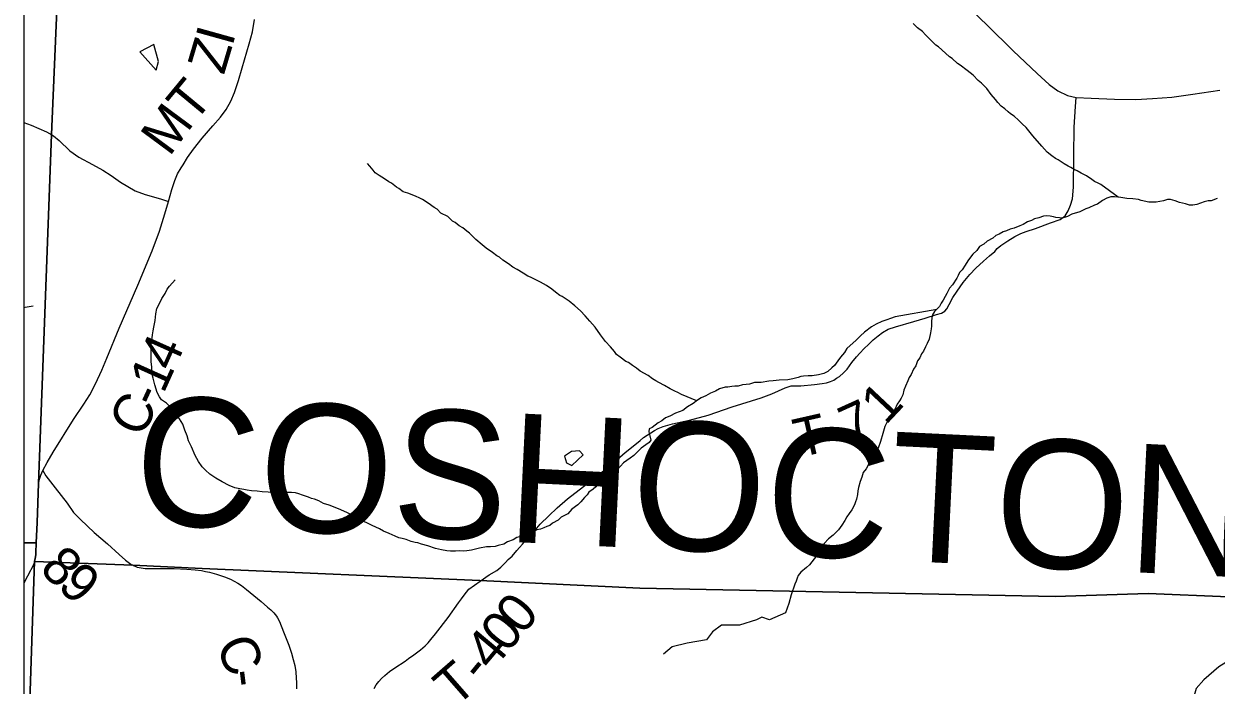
# Model space of a CAD drawing. Extents: x 0 to 34, y 0 to 22.
# Drawn here: x 2.1 to 3.853, y 16.238 to 17.211 of the extents above; entities that cross this region are included whole.
import ezdxf

# ---------------------------------------------------------------- set-up
doc = ezdxf.new("R2010")
doc.units = 0
for name, color, linetype in [('GM_X_Corporation', 7, 'Continuous'), ('GM_X_County_Road', 7, 'Continuous'), ('GM_X_County_Road_Text', 7, 'Continuous'), ('GM_X_County_Text', 7, 'Continuous'), ('GM_X_Minor_Lake', 7, 'Continuous'), ('GM_X_Minor_River', 7, 'Continuous'), ('GM_X_Township_Road', 7, 'Continuous'), ('GM_X_Township_Road_Text', 7, 'Continuous'), ('SH_Data', 7, 'Continuous')]:
    doc.layers.add(name, color=color, linetype=linetype)

msp = doc.modelspace()

# ---------------------------------------------------------------- linework, layer by layer
at = {"layer": 'GM_X_Corporation'}
for points in [[(8.9, 20.9), (2.1, 20.9), (2.1, 16.4477), (2.1182, 16.4474), (2.1176, 16.4327), (2.1175, 16.4298), (2.1166, 16.4244), (2.1155, 16.4201), (2.2605, 16.4147), (2.3623, 16.41), (2.7707, 16.392), (3.0057, 16.3809), (3.6165, 16.3686), (3.7537, 16.3728), (3.9899, 16.3631), (4.4958, 16.358), (4.9914, 16.3477), (5.6931, 16.3352)], [(2.1, 20.9), (2.1, 16.4477), (2.1182, 16.4474), (2.1195, 16.4774), (2.1214, 16.5347), (2.1408, 17.0483), (2.1838, 18.0574), (2.1889, 18.2792), (2.187, 18.2863), (2.1862, 18.2947), (2.1862, 18.3057), (2.1873, 18.3376), (2.1879, 18.3572), (2.1884, 18.4113), (2.1894, 18.4715), (2.1995, 18.7384)], [(2.1838, 18.0574), (2.1408, 17.0483), (2.1214, 16.5347), (2.1195, 16.4774), (2.1182, 16.4474), (2.1176, 16.4327), (2.1175, 16.4298), (2.1166, 16.4244), (2.1155, 16.4201), (2.2605, 16.4147), (2.3623, 16.41), (2.7707, 16.392), (3.0057, 16.3809), (3.6165, 16.3686), (3.7537, 16.3728), (3.9899, 16.3631)], [(5.6931, 16.3352), (4.9914, 16.3477), (4.4958, 16.358), (3.9899, 16.3631), (3.7537, 16.3728), (3.6165, 16.3686), (3.0057, 16.3809), (2.7707, 16.392), (2.3623, 16.41), (2.2605, 16.4147), (2.1155, 16.4201), (2.1166, 16.4244), (2.1175, 16.4298), (2.1176, 16.4327), (2.1182, 16.4474), (2.1, 16.4477), (2.1, 14.1)], [(8.9, 14.5591), (8.9, 16.2485), (8.785, 16.2515), (8.0233, 16.275), (7.0491, 16.2993), (7.0302, 16.2995), (6.9309, 16.303), (5.9938, 16.3204), (5.6931, 16.3352), (4.9914, 16.3477), (4.4958, 16.358), (3.9899, 16.3631), (3.7537, 16.3728), (3.6165, 16.3686), (3.0057, 16.3809), (2.7707, 16.392), (2.3623, 16.41), (2.2605, 16.4147), (2.1155, 16.4201), (2.1, 15.9517)]]:
    msp.add_lwpolyline(points, dxfattribs=at)
msp.add_lwpolyline([(2.1, 16.4477), (2.1, 15.9517), (2.1155, 16.4201), (2.1166, 16.4244), (2.1175, 16.4298), (2.1176, 16.4327), (2.1182, 16.4474)], close=True, dxfattribs=at)
at = {"layer": 'GM_X_County_Road'}
for points in [[(3.4731, 17.2516), (3.5167, 17.2094), (3.5551, 17.1716), (3.5904, 17.1379), (3.6078, 17.1217), (3.6208, 17.1126), (3.635, 17.1059), (3.6476, 17.1027)], [(2.1281, 16.5538), (2.1345, 16.5659), (2.143, 16.5809), (2.1729, 16.6292), (2.1883, 16.6518), (2.1972, 16.6651), (2.2054, 16.6814), (2.2148, 16.7015), (2.222, 16.7192), (2.2402, 16.7634), (2.2677, 16.8268), (2.2889, 16.8773), (2.2994, 16.9063), (2.3073, 16.9316), (2.3128, 16.95), (2.3177, 16.9674), (2.3222, 16.9805), (2.3261, 16.9903), (2.3314, 16.9993), (2.3343, 17.0036), (2.3407, 17.0147), (2.3493, 17.027), (2.3621, 17.0432), (2.3778, 17.0613), (2.3892, 17.0739), (2.3974, 17.0853), (2.4046, 17.0976), (2.4099, 17.1102), (2.4157, 17.1277), (2.4213, 17.1464), (2.4315, 17.1818), (2.4363, 17.1992), (2.4391, 17.2176)], [(3.6476, 17.1027), (3.6697, 17.1016), (3.704, 17.1004), (3.7355, 17.1), (3.7599, 17.1012), (3.7883, 17.1031), (3.819, 17.1079), (3.8589, 17.1138)], [(2.1184, 16.4468), (2.1197, 16.4768), (2.1216, 16.5341), (2.123, 16.541), (2.1248, 16.5472), (2.1281, 16.5538)], [(2.1281, 16.5538), (2.1325, 16.5463), (2.1461, 16.5287), (2.1635, 16.5057), (2.1732, 16.4921), (2.1834, 16.4817), (2.2036, 16.463), (2.2231, 16.446), (2.2401, 16.4302), (2.2495, 16.4221), (2.2592, 16.4146)], [(2.1157, 16.4196), (2.1168, 16.4238), (2.1177, 16.4293), (2.1178, 16.4321), (2.1184, 16.4468)], [(2.2607, 16.4142), (2.2638, 16.4131), (2.2666, 16.412), (2.2694, 16.4112), (2.2724, 16.4106), (2.2784, 16.4099), (2.2875, 16.4096), (2.3121, 16.4097), (2.3213, 16.4096), (2.3306, 16.4093), (2.3398, 16.4088), (2.352, 16.4079), (2.3611, 16.4067), (2.3672, 16.4056), (2.3732, 16.4043), (2.3833, 16.4013), (2.3951, 16.3973), (2.4038, 16.3939), (2.4095, 16.3912), (2.4149, 16.3881), (2.4201, 16.3846), (2.4275, 16.3789), (2.449, 16.361), (2.4584, 16.353), (2.4631, 16.3489), (2.4676, 16.3445), (2.4696, 16.3422), (2.4715, 16.3397), (2.4732, 16.3371), (2.4762, 16.3316), (2.4786, 16.3255), (2.483, 16.3144), (2.4897, 16.2968), (2.4937, 16.285), (2.4963, 16.276), (2.4983, 16.2669), (2.4998, 16.2576), (2.5006, 16.2483), (2.5009, 16.2421), (2.501, 16.2328)]]:
    msp.add_lwpolyline(points, dxfattribs=at)
at = {"layer": 'GM_X_Minor_Lake'}
for points in [[(2.291, 17.1808), (2.2706, 17.1701), (2.2945, 17.1432)], [(2.2945, 17.1432), (2.2979, 17.1557), (2.291, 17.1808)], [(2.9225, 16.5769), (2.9172, 16.583), (2.9055, 16.5818), (2.8953, 16.575)], [(2.8953, 16.575), (2.8979, 16.5651), (2.9059, 16.5613), (2.9225, 16.5769)]]:
    msp.add_lwpolyline(points, dxfattribs=at)
at = {"layer": 'GM_X_Minor_River'}
for points in [[(3.7093, 16.9561), (3.6837, 16.975), (3.6799, 16.9769), (3.6746, 16.9792), (3.6708, 16.9822), (3.6628, 16.9875), (3.6549, 16.9916), (3.6492, 16.9951), (3.6454, 16.9966), (3.6397, 17), (3.6359, 17.0019), (3.6298, 17.0053), (3.6211, 17.0109), (3.6173, 17.0132), (3.6116, 17.017), (3.6048, 17.0226), (3.5972, 17.031), (3.5838, 17.0465), (3.574, 17.0586), (3.5683, 17.0639), (3.5629, 17.0696), (3.5565, 17.0753), (3.5512, 17.0787), (3.5474, 17.0817), (3.5428, 17.0862), (3.5371, 17.09), (3.5325, 17.0953), (3.5291, 17.0999), (3.5227, 17.1074), (3.5162, 17.1158), (3.5082, 17.1241), (3.5033, 17.1279), (3.4961, 17.1358), (3.4873, 17.1426), (3.4771, 17.1502), (3.4729, 17.1529), (3.4653, 17.1604), (3.4615, 17.1627), (3.4554, 17.168), (3.4452, 17.1771), (3.4414, 17.1797), (3.4262, 17.1949), (3.4216, 17.1998), (3.4144, 17.2055), (3.4079, 17.2115)], [(3.0896, 16.6565), (3.0674, 16.666), (3.0617, 16.6687), (3.0575, 16.6709), (3.0503, 16.6743), (3.0423, 16.6789), (3.034, 16.6834), (3.0294, 16.686), (3.0245, 16.6891), (3.0184, 16.694), (3.0063, 16.7), (3.001, 16.7046), (2.9953, 16.7087), (2.9892, 16.7129), (2.9854, 16.7144), (2.977, 16.7208), (2.9714, 16.7246), (2.9687, 16.7292), (2.9626, 16.736), (2.9554, 16.7439), (2.9482, 16.7538), (2.9402, 16.7648), (2.9326, 16.7735), (2.9257, 16.7814), (2.9185, 16.789), (2.9101, 16.7962), (2.9018, 16.803), (2.8919, 16.8098), (2.8881, 16.8117), (2.8817, 16.8166), (2.8763, 16.8208), (2.8684, 16.8261), (2.8596, 16.831), (2.8528, 16.8344), (2.8452, 16.8386), (2.8414, 16.8401), (2.8342, 16.8442), (2.8255, 16.8499), (2.819, 16.8533), (2.8126, 16.8582), (2.8046, 16.8635), (2.7993, 16.8681), (2.7955, 16.8699), (2.789, 16.8749), (2.7799, 16.8809), (2.7742, 16.8858), (2.7647, 16.8938), (2.7552, 16.9032), (2.7514, 16.9059), (2.7457, 16.9108), (2.74, 16.9142), (2.7343, 16.9191), (2.7305, 16.9206), (2.7233, 16.9275), (2.7131, 16.9328), (2.7078, 16.9384), (2.7036, 16.9407), (2.6948, 16.9471), (2.6861, 16.9528), (2.6812, 16.9551), (2.677, 16.957), (2.6687, 16.9607), (2.6649, 16.9619), (2.658, 16.9641), (2.6516, 16.969), (2.6478, 16.9709), (2.6406, 16.9766), (2.6368, 16.9789), (2.6303, 16.983), (2.6224, 16.988), (2.6167, 16.9921), (2.6136, 16.9959), (2.6087, 17.002), (2.6056, 17.0058)], [(3.855, 16.9542), (3.846, 16.9507), (3.8418, 16.9507), (3.8357, 16.9492), (3.8251, 16.9454), (3.8191, 16.9442), (3.8145, 16.9442), (3.8085, 16.9461), (3.7994, 16.9483), (3.7933, 16.9506), (3.7861, 16.9525), (3.7819, 16.9529), (3.7759, 16.9509), (3.7653, 16.949), (3.7584, 16.9486), (3.7546, 16.949), (3.7433, 16.9513), (3.7395, 16.9528), (3.7311, 16.9535), (3.722, 16.9542), (3.7133, 16.9557), (3.7042, 16.9565), (3.6985, 16.9565), (3.6929, 16.9549), (3.6864, 16.9511), (3.6789, 16.9458), (3.6747, 16.9443), (3.666, 16.9405), (3.6618, 16.9389), (3.6528, 16.9347), (3.6414, 16.9313), (3.635, 16.9279), (3.627, 16.9252), (3.6229, 16.9256), (3.6179, 16.9263), (3.6141, 16.9274), (3.6092, 16.9282), (3.6035, 16.9286), (3.5994, 16.9282), (3.5929, 16.9259), (3.5865, 16.9244), (3.5819, 16.9217), (3.5759, 16.9198), (3.5698, 16.916), (3.5649, 16.9141), (3.5566, 16.9106), (3.5505, 16.9091), (3.5449, 16.9064), (3.5403, 16.9053), (3.5346, 16.9019), (3.5297, 16.8996), (3.5252, 16.8958), (3.5169, 16.8916), (3.5116, 16.887), (3.5055, 16.8836), (3.5017, 16.8779), (3.4957, 16.8722), (3.4923, 16.868), (3.4885, 16.8623), (3.4844, 16.8562), (3.4799, 16.849), (3.4761, 16.8452), (3.4742, 16.841), (3.4719, 16.8372), (3.4659, 16.8274), (3.4614, 16.8224), (3.4595, 16.8182), (3.4576, 16.8144), (3.455, 16.8099), (3.4519, 16.8046), (3.4493, 16.8004), (3.4467, 16.7954), (3.4395, 16.7878), (3.4365, 16.7829), (3.4354, 16.7787), (3.435, 16.773), (3.4346, 16.7662), (3.4343, 16.7624), (3.4335, 16.7563), (3.4313, 16.7472), (3.4283, 16.7408), (3.426, 16.7358), (3.423, 16.7294), (3.42, 16.7256), (3.4177, 16.7199), (3.4143, 16.7153), (3.4117, 16.7081), (3.4083, 16.7032)], [(2.7585, 16.437), (2.7517, 16.4358), (2.746, 16.4354), (2.7407, 16.4358), (2.735, 16.4354), (2.7274, 16.4354), (2.7221, 16.4357), (2.7142, 16.4372), (2.7054, 16.4391), (2.6941, 16.4433), (2.6846, 16.4455), (2.6793, 16.4478), (2.6755, 16.4482), (2.6694, 16.4497), (2.6622, 16.4523), (2.6565, 16.4538), (2.6516, 16.4549), (2.6459, 16.4572), (2.6372, 16.4614), (2.6288, 16.4648), (2.6231, 16.4682), (2.6178, 16.4708), (2.6125, 16.4731), (2.6034, 16.4776), (2.5943, 16.481), (2.5859, 16.4867), (2.5761, 16.4916), (2.5662, 16.4961), (2.5579, 16.4995), (2.5488, 16.5029), (2.5408, 16.5056), (2.5336, 16.5093), (2.5275, 16.5116), (2.523, 16.5127), (2.5188, 16.5146), (2.5097, 16.5176), (2.5044, 16.5195), (2.4994, 16.521), (2.4938, 16.5214), (2.4866, 16.5214), (2.4786, 16.521), (2.4748, 16.521), (2.468, 16.5213), (2.4593, 16.5221), (2.4506, 16.5225), (2.443, 16.5236), (2.4346, 16.5243), (2.4286, 16.5251), (2.4233, 16.5258), (2.4176, 16.5269), (2.4104, 16.5284), (2.402, 16.5318), (2.3918, 16.5371), (2.3823, 16.5428), (2.3736, 16.5485), (2.3671, 16.5545), (2.3622, 16.5595), (2.3568, 16.567), (2.3519, 16.5761), (2.3465, 16.589), (2.342, 16.5974), (2.3401, 16.6049), (2.337, 16.6133), (2.3336, 16.622), (2.329, 16.63), (2.326, 16.6337), (2.3225, 16.639), (2.318, 16.6447), (2.3096, 16.6531), (2.3024, 16.658), (2.2993, 16.6625), (2.2959, 16.6686), (2.2928, 16.68), (2.2902, 16.6898), (2.2886, 16.6951), (2.2882, 16.6993), (2.2882, 16.7058), (2.2874, 16.7145), (2.287, 16.7221), (2.287, 16.7357), (2.2874, 16.7403), (2.2877, 16.7441), (2.2889, 16.749), (2.2892, 16.7536), (2.29, 16.7593), (2.2911, 16.765), (2.2929, 16.7748), (2.2941, 16.7847), (2.2955, 16.7923), (2.2993, 16.7999), (2.3031, 16.8071), (2.3076, 16.8143), (2.3106, 16.8208), (2.314, 16.8253), (2.3223, 16.8344)], [(2.1, 16.7939), (2.1019, 16.7945), (2.1137, 16.7961)], [(3.4426, 16.7911), (3.3815, 16.7801), (3.3744, 16.7778), (3.3691, 16.7759), (3.3619, 16.7733), (3.3535, 16.7694), (3.3467, 16.7656), (3.3361, 16.7573), (3.3305, 16.7519), (3.3237, 16.7455), (3.3154, 16.7379), (3.3104, 16.7333), (3.3067, 16.7276), (3.301, 16.7208), (3.2969, 16.7151), (3.292, 16.7086), (3.2882, 16.7048), (3.2825, 16.6995), (3.2765, 16.6968), (3.2689, 16.6949), (3.2594, 16.6934), (3.2537, 16.6933), (3.2465, 16.6926), (3.2427, 16.6922), (3.2386, 16.691), (3.231, 16.6891), (3.2238, 16.6876), (3.2109, 16.6868), (3.2022, 16.686), (3.1954, 16.6853), (3.1844, 16.6837), (3.1787, 16.6837), (3.1746, 16.6833), (3.167, 16.681), (3.1621, 16.6806), (3.1568, 16.6799), (3.1507, 16.6783), (3.1458, 16.6779), (3.1412, 16.6776), (3.1352, 16.6768), (3.1314, 16.6764), (3.1231, 16.6741), (3.1174, 16.6707), (3.1098, 16.6676), (3.103, 16.6638), (3.0962, 16.6611), (3.0909, 16.6573), (3.0841, 16.6528), (3.0762, 16.6478), (3.069, 16.6425), (3.0584, 16.6383), (3.0501, 16.6341), (3.0436, 16.6314), (3.0383, 16.6273), (3.033, 16.6242), (3.024, 16.6174), (3.0194, 16.6151), (3.0191, 16.6109), (3.0206, 16.6048), (3.0221, 16.5988), (3.0195, 16.595), (3.0149, 16.5919), (3.0081, 16.587), (2.9972, 16.5759), (2.9919, 16.5721), (2.9821, 16.5653), (2.973, 16.5554), (2.9616, 16.547), (2.9533, 16.5413), (2.9465, 16.5375), (2.9412, 16.5299), (2.9371, 16.5265), (2.931, 16.5219), (2.9284, 16.5181), (2.9246, 16.5143), (2.9189, 16.5079), (2.9148, 16.5037), (2.9061, 16.4972), (2.9, 16.4904), (2.8902, 16.4854), (2.8857, 16.4809), (2.8777, 16.4763), (2.8736, 16.4729), (2.869, 16.4717), (2.8649, 16.4698), (2.86, 16.4679), (2.8546, 16.4668), (2.8471, 16.4622), (2.8395, 16.4595), (2.8331, 16.4576), (2.8248, 16.4553), (2.8198, 16.4519), (2.8111, 16.4488), (2.8058, 16.4454), (2.7975, 16.4435), (2.7933, 16.4423), (2.7861, 16.4419), (2.7805, 16.4419), (2.7702, 16.4396), (2.7661, 16.4389), (2.7585, 16.437)], [(3.4083, 16.7032), (3.4049, 16.6952), (3.4019, 16.691), (3.4, 16.6857), (3.3966, 16.6781), (3.3944, 16.672), (3.3925, 16.6652), (3.3902, 16.6603), (3.388, 16.6565), (3.3842, 16.6515), (3.3808, 16.6439), (3.3748, 16.6352), (3.3699, 16.6264), (3.3661, 16.6185), (3.3635, 16.6082), (3.3597, 16.5965), (3.3563, 16.587), (3.3533, 16.5813), (3.3499, 16.5767), (3.3469, 16.5706), (3.3428, 16.5638), (3.3386, 16.5566), (3.3345, 16.5509), (3.3322, 16.5444), (3.33, 16.5376), (3.3277, 16.5292), (3.3266, 16.5243), (3.3259, 16.5186), (3.3244, 16.5118), (3.3232, 16.508), (3.3214, 16.5034), (3.3176, 16.4962), (3.3138, 16.4909), (3.3104, 16.4859), (3.3074, 16.4806), (3.3029, 16.4738), (3.298, 16.4669), (3.29, 16.459), (3.2832, 16.4536), (3.2772, 16.4464), (3.2712, 16.4373), (3.2685, 16.4335), (3.2659, 16.4286), (3.2553, 16.4152), (3.2508, 16.4111), (3.2425, 16.4042), (3.2387, 16.3993), (3.2372, 16.3955), (3.2357, 16.3913), (3.2338, 16.3867), (3.2287, 16.3712)], [(3.2287, 16.3712), (3.2252, 16.3584), (3.22, 16.3446), (3.1966, 16.3343), (3.1854, 16.3383), (3.1776, 16.3343), (3.1523, 16.3262), (3.1258, 16.3265), (3.1126, 16.3166), (3.1039, 16.3048), (3.0756, 16.3001), (3.0533, 16.2944), (3.0408, 16.2837)], [(3.9737, 16.3586), (3.9672, 16.3431), (3.9366, 16.3195), (3.9114, 16.2986), (3.8574, 16.265), (3.8355, 16.2459), (3.8242, 16.2334), (3.8078, 16.1772), (3.8019, 16.1514), (3.7947, 16.1392), (3.7838, 16.1316), (3.7626, 16.1315), (3.7271, 16.1173), (3.7142, 16.1177), (3.6823, 16.1327)]]:
    msp.add_lwpolyline(points, dxfattribs=at)
at = {"layer": 'GM_X_Township_Road'}
for points in [[(2.7709, 16.3914), (2.7841, 16.4005), (2.7958, 16.407), (2.8013, 16.4119), (2.8082, 16.4184), (2.8124, 16.423), (2.8183, 16.4277), (2.8248, 16.4361), (2.8288, 16.4408), (2.8335, 16.4456), (2.8412, 16.4552), (2.8496, 16.4634), (2.8593, 16.4751), (2.872, 16.4873), (2.8844, 16.4989), (2.8993, 16.5121), (2.9293, 16.5352), (2.9641, 16.563), (2.9842, 16.5804), (2.9984, 16.5918), (3.0066, 16.598), (3.0113, 16.6027), (3.0165, 16.606), (3.022, 16.6094), (3.0274, 16.6127), (3.0331, 16.6159), (3.0403, 16.6186), (3.0538, 16.6226), (3.0791, 16.6281), (3.1064, 16.6353), (3.1416, 16.6477), (3.1844, 16.6608), (3.2, 16.6668), (3.2194, 16.6757), (3.2286, 16.6784), (3.2425, 16.6785), (3.2628, 16.6805), (3.2742, 16.6822), (3.2802, 16.6832), (3.2864, 16.6847), (3.2911, 16.6867), (3.2953, 16.6899), (3.2996, 16.6924), (3.3053, 16.6976), (3.311, 16.7031), (3.3179, 16.7127), (3.3244, 16.7212), (3.3294, 16.7266), (3.3358, 16.7333), (3.342, 16.7396), (3.349, 16.7463), (3.3562, 16.752), (3.3629, 16.7569), (3.3713, 16.7617), (3.382, 16.7654), (3.4091, 16.7731), (3.4255, 16.7783), (3.4421, 16.7833), (3.4496, 16.7857), (3.4543, 16.7882), (3.4575, 16.792), (3.461, 16.7984), (3.4662, 16.8086), (3.4724, 16.818), (3.4816, 16.8307), (3.4913, 16.8426), (3.5002, 16.8518), (3.5111, 16.862), (3.5201, 16.8699), (3.5278, 16.8764), (3.5315, 16.8804), (3.537, 16.8848), (3.5471, 16.8918), (3.5573, 16.8985), (3.5664, 16.9027), (3.5742, 16.9054), (3.5876, 16.9101), (3.61, 16.9186), (3.6241, 16.9233), (3.6314, 16.9289), (3.636, 16.9362), (3.6393, 16.9442), (3.6421, 16.9538), (3.6437, 16.9711), (3.6444, 17.0168), (3.6448, 17.059), (3.6468, 17.0897), (3.6476, 17.1027)], [(2.1, 17.0662), (2.1107, 17.062), (2.1331, 17.0522), (2.141, 17.0478), (2.1436, 17.0463), (2.1519, 17.0394)], [(2.1519, 17.0394), (2.1677, 17.0242), (2.1808, 17.015), (2.201, 17.0041), (2.216, 16.9959), (2.2282, 16.9878), (2.2421, 16.9783), (2.2636, 16.9657), (2.2783, 16.9599), (2.3012, 16.9537), (2.3128, 16.95)], [(2.1157, 16.4196), (2.1168, 16.4238), (2.1177, 16.4293), (2.1178, 16.4321), (2.1184, 16.4468)], [(2.1, 16.3884), (2.1003, 16.3889), (2.106, 16.3989), (2.115, 16.4168), (2.1157, 16.4196)], [(2.615, 16.2333), (2.6182, 16.2386), (2.622, 16.2435), (2.6262, 16.248), (2.6307, 16.2522), (2.6379, 16.2581), (2.6454, 16.2635), (2.6607, 16.2737), (2.6658, 16.2772), (2.6733, 16.2827), (2.6831, 16.2902), (2.6902, 16.2962), (2.6945, 16.3006), (2.6986, 16.3052), (2.7053, 16.3138), (2.7241, 16.3378), (2.7391, 16.3594), (2.7436, 16.3654), (2.7478, 16.3705), (2.7546, 16.3793), (2.7709, 16.3914)]]:
    msp.add_lwpolyline(points, dxfattribs=at)
at = {"layer": 'SH_Data'}
msp.add_line((2.1, 20.9), (2.1, 14.1), dxfattribs=at)

# ---------------------------------------------------------------- texts
at = {"layer": 'GM_X_County_Road_Text'}
for s, rotation, p in [('I', 74.4599, (2.4065, 17.1767)), ('Z', 73.4725, (2.3941, 17.1349)), ('T', 50.454, (2.3502, 17.0636)), ('M', 53.4916, (2.314, 17.0146)), ('4', 65.8802, (2.3197, 16.6978)), ('1', 65.7626, (2.3053, 16.6658)), ('C', 62.9462, (2.2731, 16.6003)), ('-', 65.4829, (2.2955, 16.6443)), ('8', 316.1886, (2.1212, 16.4073)), ('9', 317.633, (2.1476, 16.382)), ('C', 293.1489, (2.3815, 16.2972)), ('-', 276.9798, (2.3987, 16.2584))]:
    msp.add_text(s, height=0.0568, rotation=rotation, dxfattribs=at).set_placement(p)
at = {"layer": 'GM_X_County_Text'}
msp.add_text('COSHOCTON COUNTY', height=0.189394, rotation=357.2115, dxfattribs=at).set_placement((2.2595, 16.4761))
at = {"layer": 'GM_X_Township_Road_Text'}
for s, rotation, p in [('1', 46.7303, (3.3672, 16.6198)), ('7', 24.3671, (3.3157, 16.5914)), ('T', 12.7868, (3.2397, 16.5728)), ('-', 13.0106, (3.2814, 16.5823)), ('0', 50.0213, (2.8329, 16.3106)), ('0', 50.0178, (2.8106, 16.284)), ('4', 49.9936, (2.7883, 16.2574)), ('T', 41.1158, (2.7346, 16.2044)), ('-', 50.5673, (2.7737, 16.2397))]:
    msp.add_text(s, height=0.0568, rotation=rotation, dxfattribs=at).set_placement(p)

doc.saveas('drawing.dxf')
